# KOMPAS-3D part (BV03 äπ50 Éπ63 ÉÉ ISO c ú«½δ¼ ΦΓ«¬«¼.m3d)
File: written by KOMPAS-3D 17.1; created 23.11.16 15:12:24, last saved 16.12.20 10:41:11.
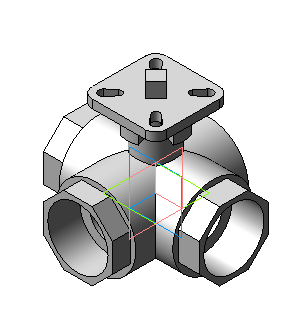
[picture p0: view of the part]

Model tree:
1. Точка:1
     X = -73.4; Координата X = -73.4
2. Операция без истории:1  (labels: Сталь 20  ГОСТ 1050-88)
